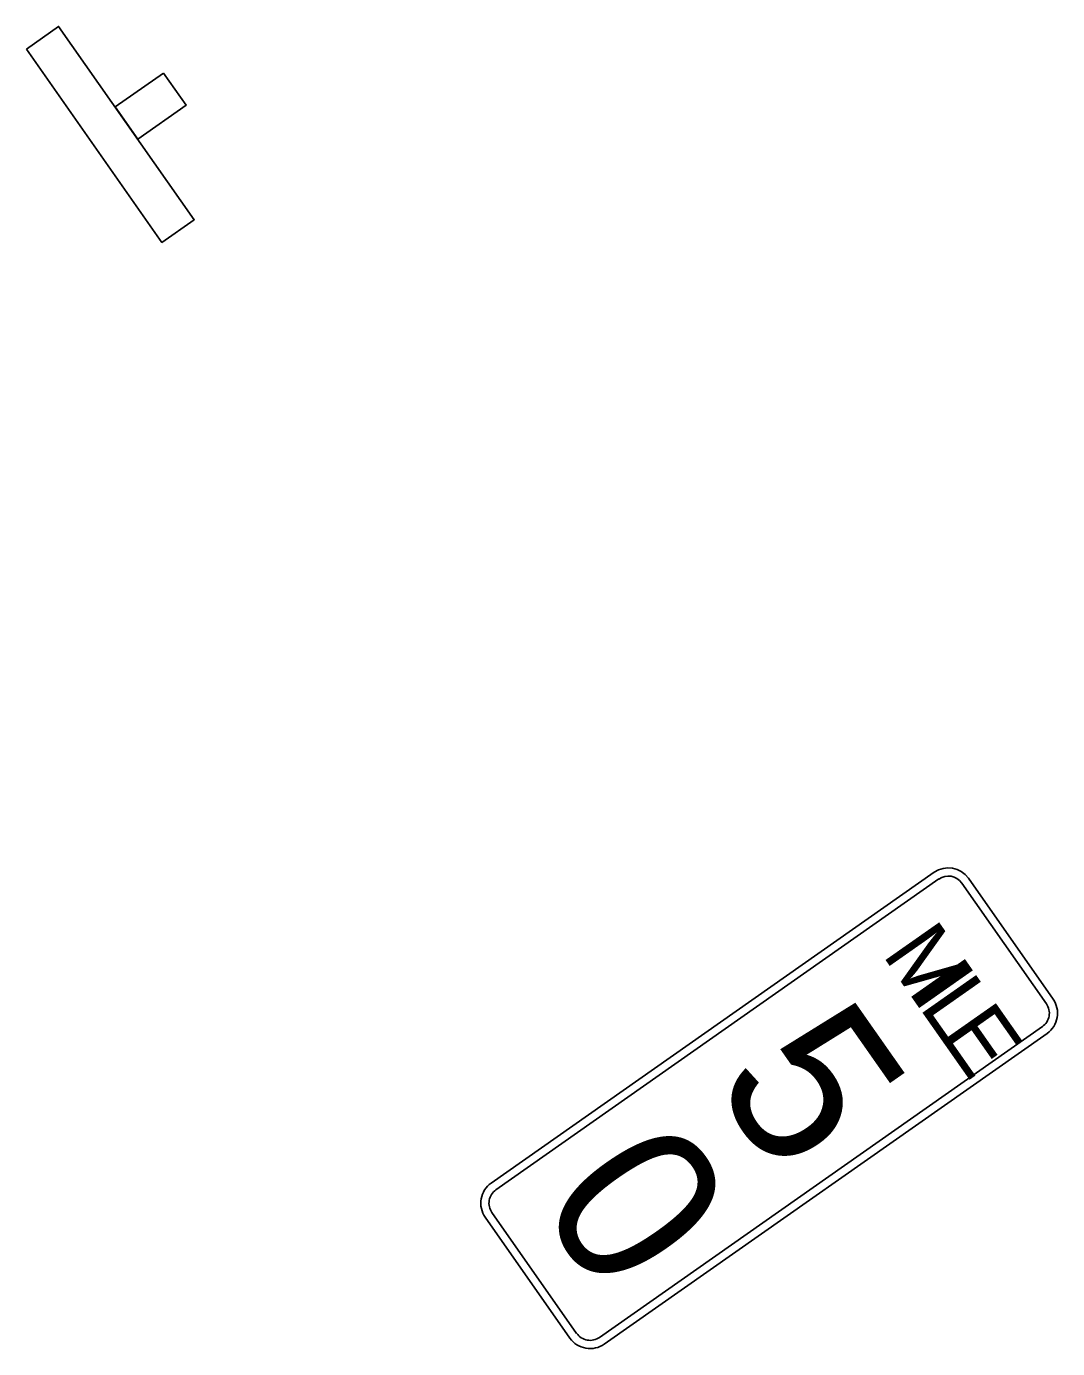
# Model space of a CAD drawing. Extents: x 1581789 to 1622364, y 1043167 to 1103486.
# Drawn here: x 1607212.2 to 1607264.6, y 1091121.4 to 1091188.6 of the extents above; entities that cross this region are included whole.
import ezdxf

# ---------------------------------------------------------------- set-up
doc = ezdxf.new("R2010")
doc.units = 0
doc.layers.add('RD_PD_ALT1_TX', color=7, linetype='Continuous')

msp = doc.modelspace()

# ---------------------------------------------------------------- linework, layer by layer
at = {"layer": 'RD_PD_ALT1_TX'}
for points in [[(1607212.174, 1091187.483), (1607219.064, 1091177.659), (1607220.702, 1091178.807), (1607213.811, 1091188.631)], [(1607219.138, 1091186.261), (1607220.287, 1091184.623), (1607217.831, 1091182.901), (1607216.682, 1091184.538)]]:
    msp.add_lwpolyline(points, close=True, dxfattribs=at)
for points in [[(1607258.316, 1091145.644), (1607235.802, 1091129.852)], [(1607235.802, 1091129.852), (1607258.316, 1091145.644)], [(1607258.555, 1091145.303), (1607236.041, 1091129.511)], [(1607264.364, 1091139.198), (1607260.057, 1091145.338)], [(1607260.057, 1091145.338), (1607264.364, 1091139.198)], [(1607264.023, 1091138.959), (1607259.716, 1091145.099)], [(1607241.305, 1091122.006), (1607263.819, 1091137.798)], [(1607241.545, 1091121.665), (1607264.058, 1091137.457)], [(1607264.058, 1091137.457), (1607241.545, 1091121.665)], [(1607235.497, 1091128.111), (1607239.803, 1091121.971)], [(1607239.803, 1091121.971), (1607235.497, 1091128.111)], [(1607235.838, 1091128.35), (1607240.144, 1091122.21)]]:
    msp.add_lwpolyline(points, dxfattribs=at)
for centre, radius, start, end in [((1607259.034, 1091144.62), 1.25, 35.04704, 125.04668), ((1607259.034, 1091144.62), 1.25, 35.04704, 125.04668), ((1607259.034, 1091144.62), 0.833, 35.04704, 125.04668), ((1607263.34, 1091138.48), 0.833, 305.04683, 35.04704), ((1607263.34, 1091138.48), 1.25, 305.04683, 35.04704), ((1607263.34, 1091138.48), 1.25, 305.04683, 35.04704), ((1607236.52, 1091128.829), 1.25, 125.04668, 215.04689), ((1607236.52, 1091128.829), 1.25, 125.04668, 215.04689), ((1607236.52, 1091128.829), 0.833, 125.04668, 215.04689), ((1607240.827, 1091122.688), 1.25, 215.04689, 305.0471), ((1607240.827, 1091122.688), 1.25, 215.04689, 305.0471), ((1607240.827, 1091122.688), 0.833, 215.04689, 305.0471)]:
    msp.add_arc(centre, radius, start, end, dxfattribs=at)

# ---------------------------------------------------------------- texts
for s, height, p in [('M', 3.333, (1607255.634, 1091141.486)), ('I', 3.333, (1607256.917, 1091139.656)), ('L', 3.333, (1607257.513, 1091138.806)), ('5', 8.333, (1607246.958, 1091134.989)), ('E', 3.333, (1607258.518, 1091137.374)), ('0', 8.333, (1607238.014, 1091128.875))]:
    msp.add_text(s, height=height, rotation=305.04683, dxfattribs=at).set_placement(p)

doc.saveas('drawing.dxf')
